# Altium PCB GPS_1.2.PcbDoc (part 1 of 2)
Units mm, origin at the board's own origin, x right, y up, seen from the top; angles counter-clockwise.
Board outline 48.01 x 70.36 mm, 4 copper layers (Top Layer, GND, VDD, Bottom Layer); 58 components, 49 nets, 268 pads, 156 vias.
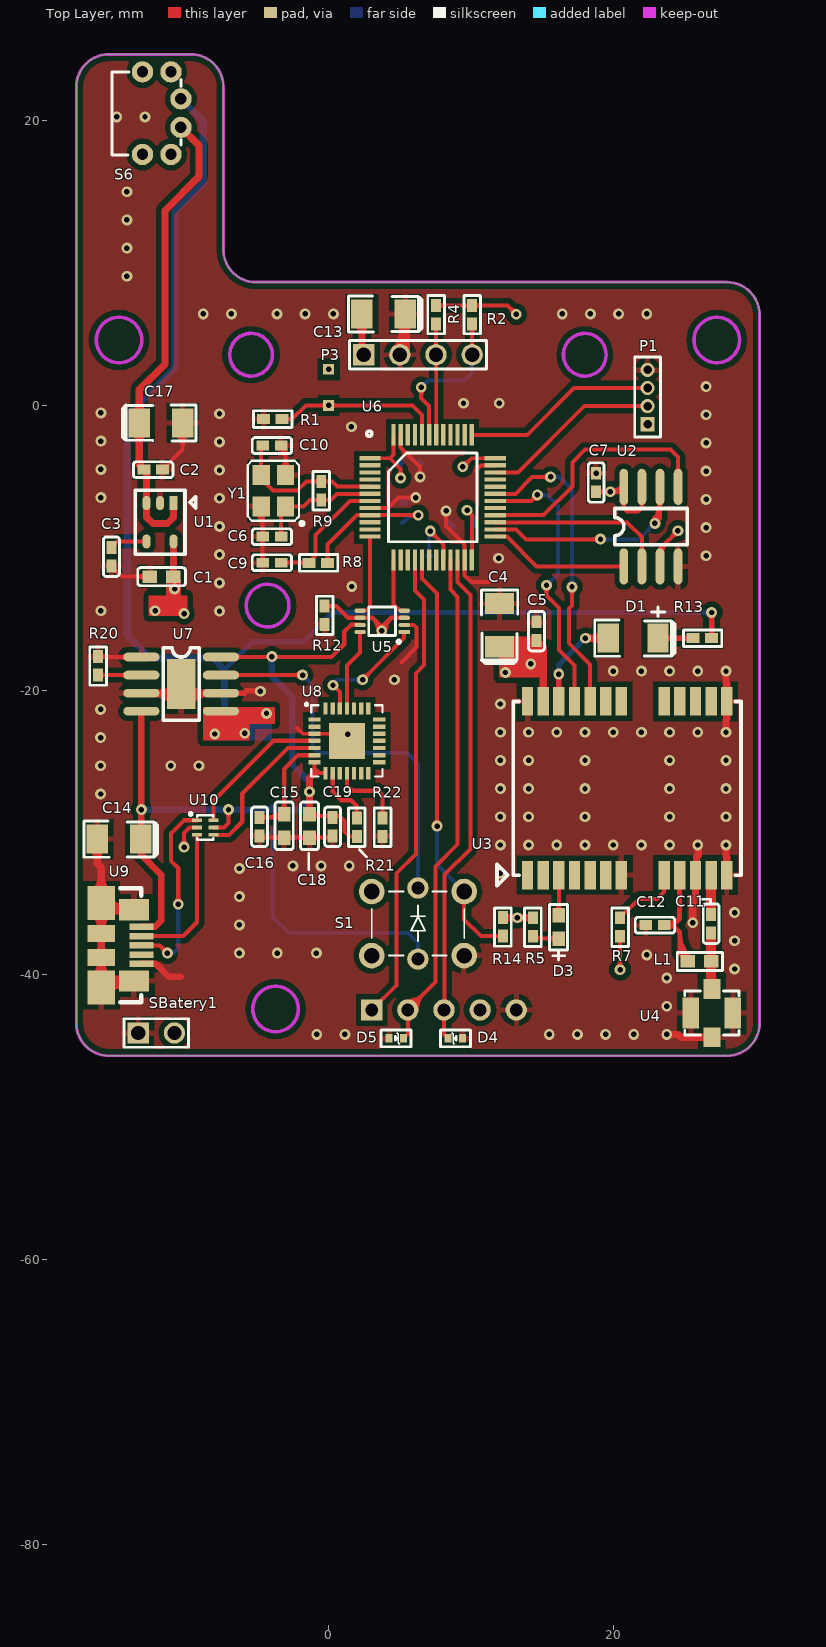
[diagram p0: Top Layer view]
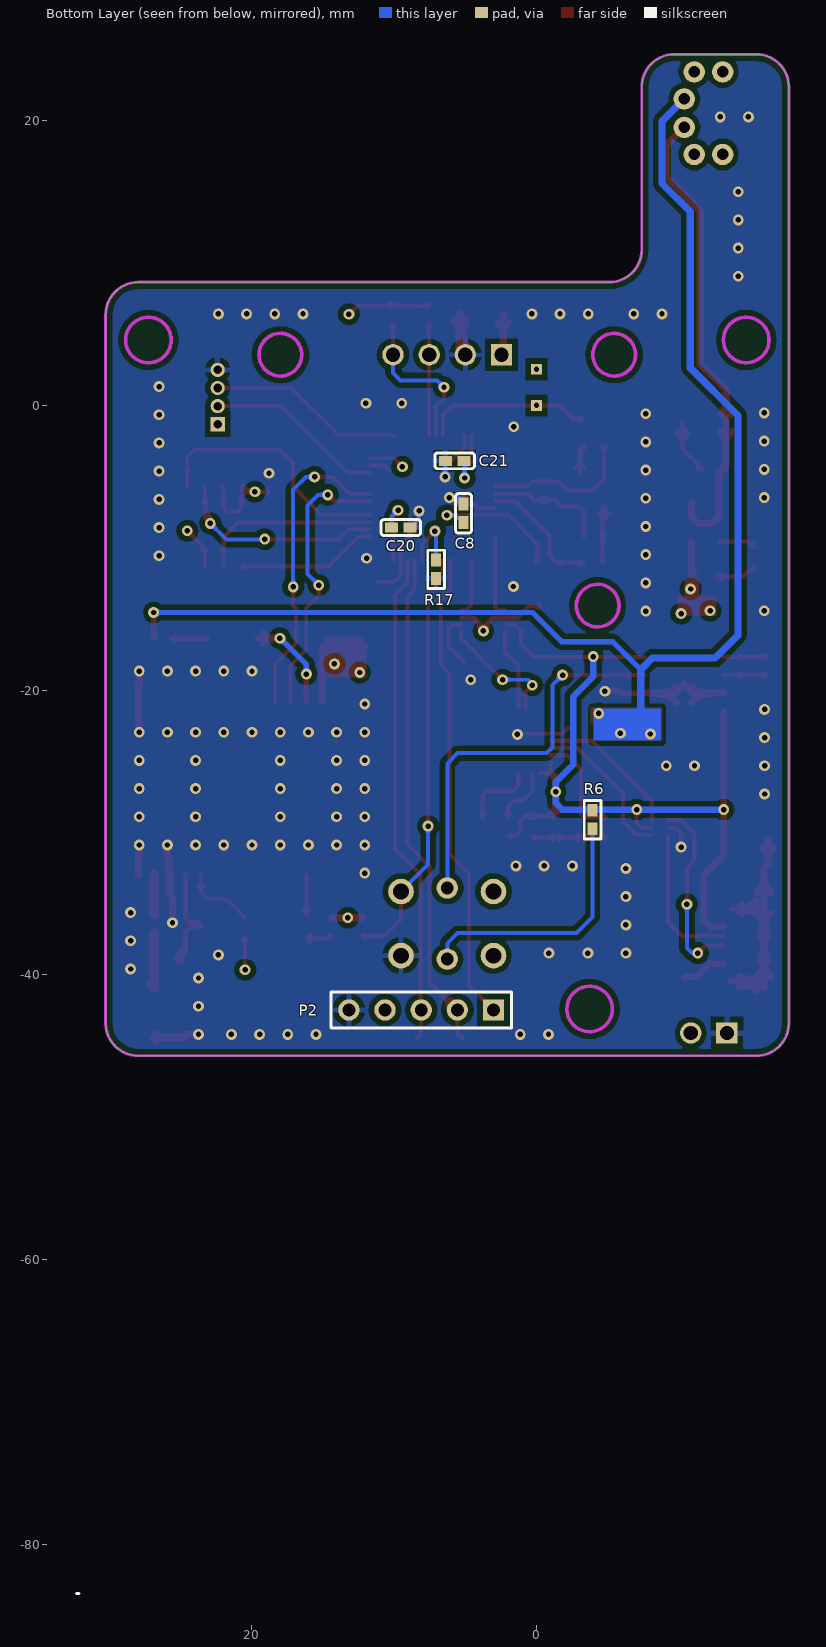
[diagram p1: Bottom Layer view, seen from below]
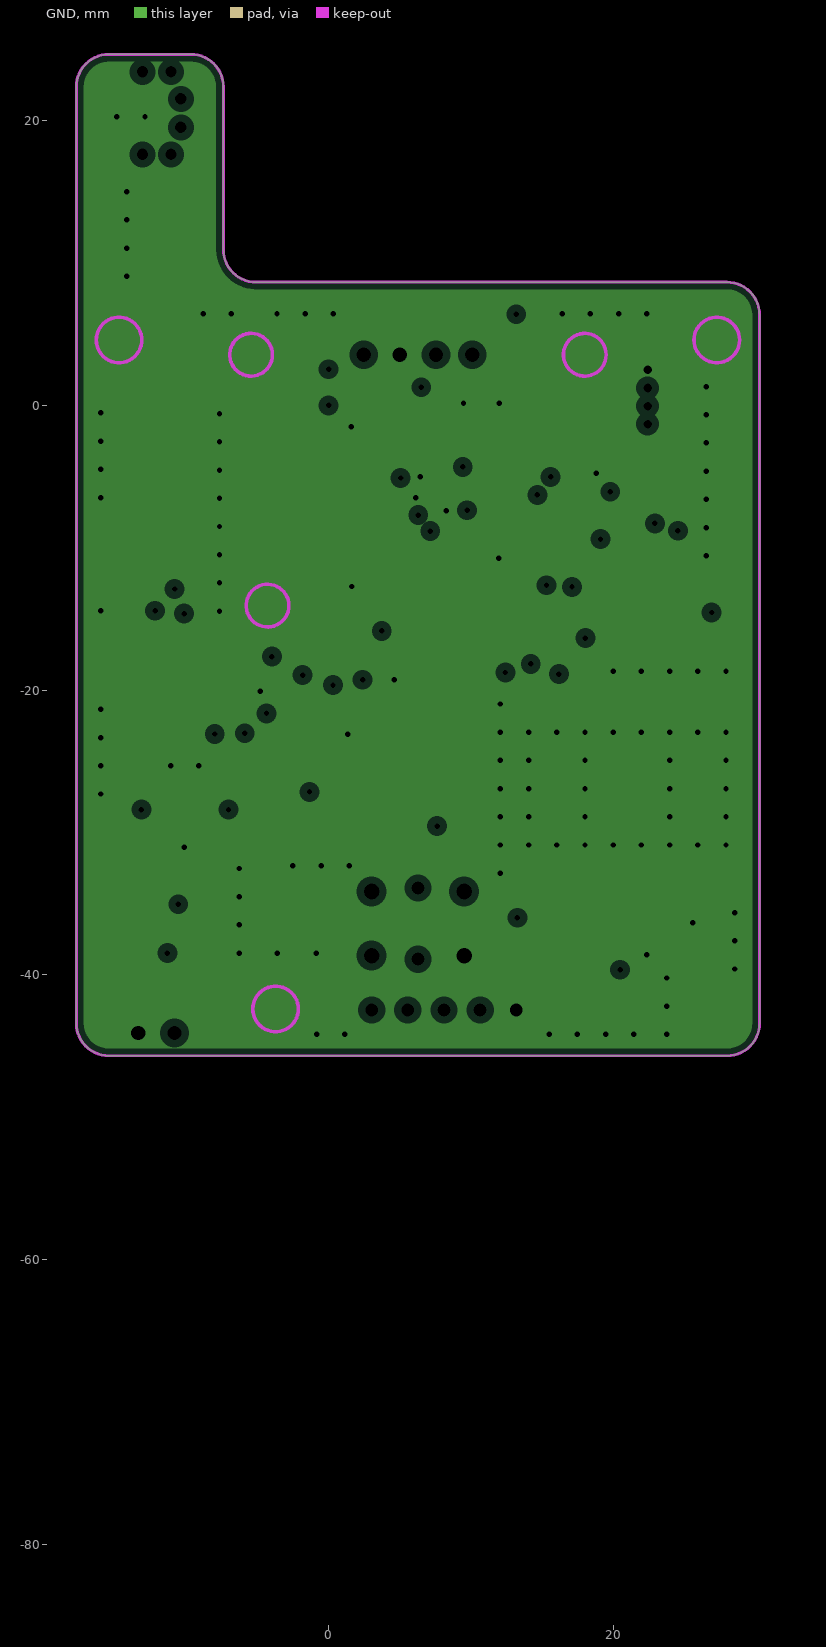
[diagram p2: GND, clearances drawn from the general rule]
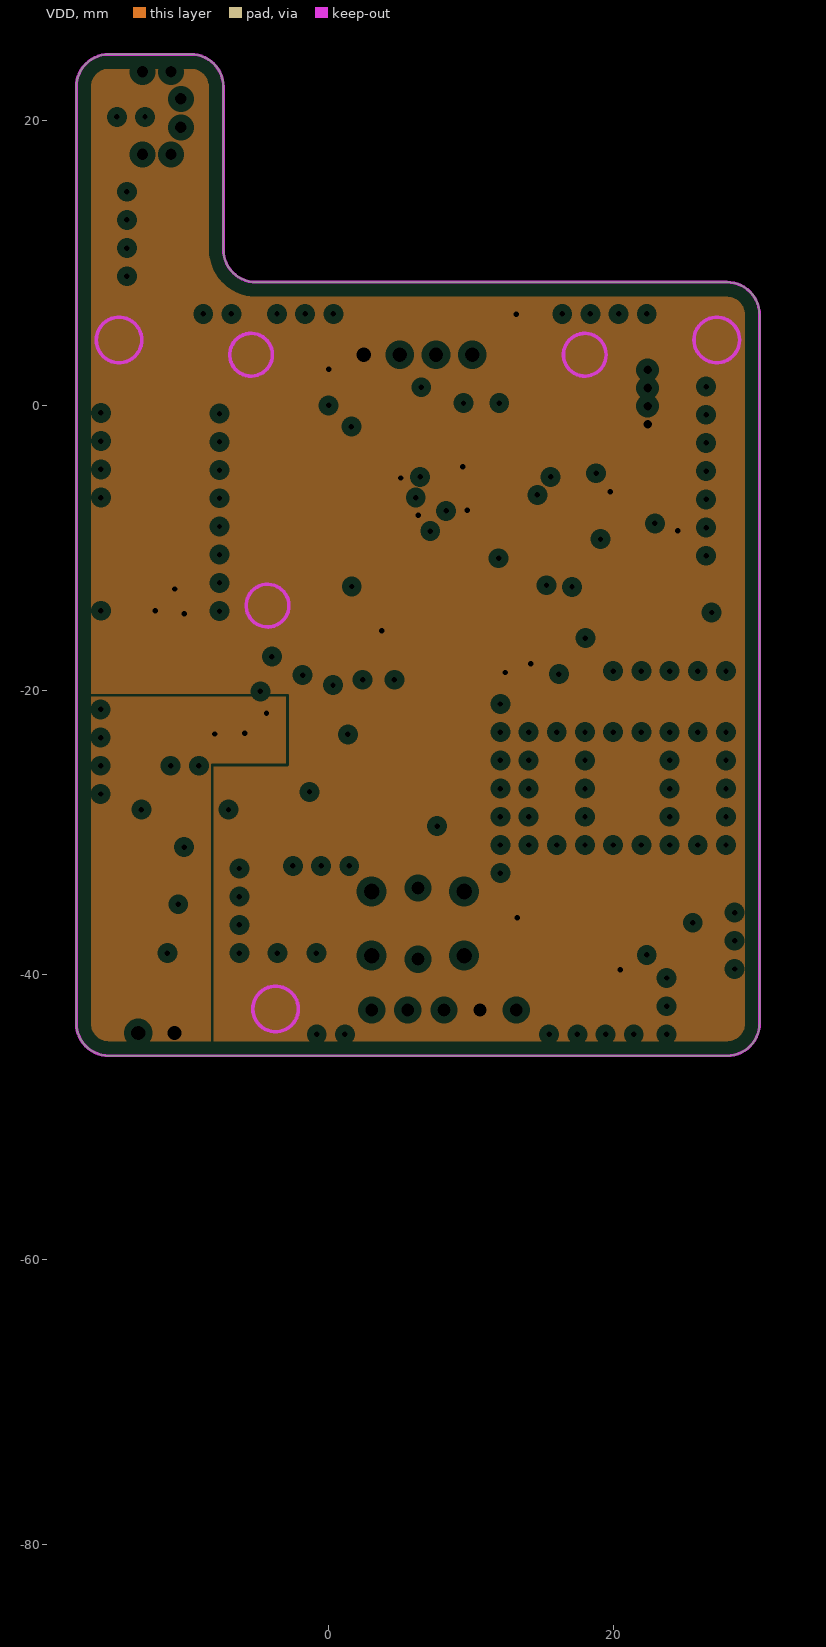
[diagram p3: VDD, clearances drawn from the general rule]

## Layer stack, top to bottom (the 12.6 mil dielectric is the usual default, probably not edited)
Top Layer: signal copper 0.0356
Dielectric: core 0.32, FR-4, Dk 4.8
GND: plane copper 0.0356, net GND
Dielectric: prepreg 0.32, FR-4, Dk 4.8
VDD: plane copper 0.0356, net VDD
Dielectric: core 0.32, FR-4, Dk 4.8
Bottom Layer: signal copper 0.0356

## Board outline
-17.729,-43.409 -17.729,22.377 cw(c-15.443,22.377) -15.443,24.663 -9.677,24.663 cw(c-9.677,22.377) -7.391,22.377 -7.391,10.939 ccw(c-5.105,10.939) -5.105,8.653 27.985,8.653 cw(c27.985,6.367) 30.271,6.367 30.271,-43.409 30.277,-43.409 cw(c27.991,-43.409) 27.991,-45.695 -15.443,-45.695 cw(c-15.443,-43.409)

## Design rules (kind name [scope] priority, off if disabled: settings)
Clearance Clearance_1 [OnLayer('Keep-Out Layer')] p1 off: gap=0.508
Clearance Clearance_RF [InNetClass('RF')] p2 off: gap=0.508
Clearance [All] p3: gap=0.381
DiffPairsRouting [All] p1: maxlimit=0.254 minlimit=0.254 mostfreqgap=0.254 maxuncoupledlength=12.7
HoleSize [All] p1 off: absolutevalues=TRUE maxlimit=2.54 minlimit=0.025 maxpercent=80.000 minpercent=20.000
HoleToHoleClearance [All] p1 off: gap=0.254 allowstackedmicrovias=TRUE
LayerPairs [All] p1 off: enforce=TRUE
MinimumSolderMaskSliver [All] p1 off: minsoldermaskwidth=0.254
NetAntennae [All] p1 off: netantennaetolerance=0
PlaneClearance [All] p1: clearance=0.508
PlaneConnect [All] p1: planeconnectstyle=Relief reliefexpansion=0.508 reliefentries=4 reliefconductorwidth=0.381 reliefairgap=0.254
PolygonConnect PolygonConnect_1 [(InPadClass('All Pads'))] p1: connectstyle=Relief reliefconductorwidth=0.381 reliefentries=4 polygonreliefangle="90 Angle"
PolygonConnect [All] p2: connectstyle=Direct reliefconductorwidth=0.381 reliefentries=4 polygonreliefangle="90 Angle"
RoutingVias [All] p1: holewidth=0.711 width=1.27 viastyle="Through Hole" minholewidth=0 minwidth=0 maxholewidth=0.711 maxwidth=1.27
SilkToSilkClearance [All] p1 off: silktosilkclearance=0.254
SilkscreenOverComponentPads [All] p1 off: minsilkscreentomaskgap=0.254
SolderMaskExpansion [All] p1: expansion=0.102
Width [All] p1: maxlimit=1.27 minlimit=0.279 preferedwidth=0.279
18 further rules are at their usual default settings.

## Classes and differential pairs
net class RF: NetC11_1 RF_IN
differential pair D: +D_P -D_N

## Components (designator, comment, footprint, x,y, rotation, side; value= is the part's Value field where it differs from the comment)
C1 "10uF/10V" C0603 -11.735,-12.04 r0 top
C2 "0.1uF/10V" C0402 -12.979,-4.521 r180 top
C3 "0.01uF/10V" C0402 -15.265,-9.982 r90 top
C4 "10uF/10V" 3528 12.014,-16.967 r90 top
C5 "0.1uF/10V" C0402 14.605,-16.51 r270 top
C6 "18pF/10V" C0402 -4.635,-9.228 r180 top
C7 "0.01uF/10V" C0402 18.796,-6.071 r270 top
C8 "0.01uF/10V" C0402 5.131,-8.238 r270 bottom
C9 "0.01uF/10V" C0402 -4.635,-11.057 r180 top
C10 "18pF/10V" C0402 -3.335,-2.827 r0 top
C11 "470pF" C0402 26.873,-37.067 r270 top
C12 "33nF" C0402 22.276,-36.525 r180 top
C13 "10uF/10V" C1206 3.861,6.426 r180 top
C14 "10uF/10V" 3528 -13.208,-30.48 r180 top
C15 "4.7uF/10V" C0603 -3.124,-29.54 r90 top
C16 "0.1uF/10V" C0402 -4.851,-28.956 r90 top
C17 "10uF/10V" 3528 -13.31,-1.245 r0 top
C18 "10uF/10V" C0603 -1.346,-29.54 r270 top
C19 "0.1uF/10V" C0402 0.279,-28.956 r90 top
C20 "0.01uF/10V" C0402 10.185,-8.585 r0 bottom
C21 "0.01uF/10V" C0402 5.105,-3.894 r180 bottom
D1 "IN4148" L1206 23.139,-16.358 r180 top
D3 "LED0" LED0603 16.154,-37.473 r90 top
D4 "PESD0402-140" 0402-TVS 8.077,-44.425 r180 top
D5 "PESD0402-140" 0402-TVS 5.563,-44.526 r0 top
L1 "6.8nH" R0603 26.06,-39.065 r180 top
P1 "MHDR1X4" SIP4_1.27 22.403,-1.321 r0 top
P2 "Header 5" HDR1X5 3.023,-42.477 r0 bottom
P3 "MHDR1X4" OLED 6.271,3.556 r0 top locked
R1 "10K/5%" R0402 -3.272,-0.965 r0 top
R2 "5.1K/5%" R0402 10.084,5.715 r270 top
R4 "5.1K/5%" R0402 7.544,5.715 r270 top
R5 "510R/5%" R0402 14.351,-36 r90 top
R6 "1K/5%" R0402 -3.937,-28.448 r90 bottom
R7 "10K/5%" R0402 20.472,-36 r90 top
R8 "10K/5%" R0402 -1.372,-11.074 r180 top
R9 "1M/5%" R0402 -0.521,-5.342 r90 top
R12 "10K/5%" R0402 -0.279,-14.097 r90 top
R13 "105K/5%" R0402 25.603,-16.358 r180 top
R14 "10K/5%" R0402 12.243,-35.992 r90 top
R17 "10K/5%" R0402 7.058,-10.866 r90 bottom
R20 "2K/5%" R0402 -16.205,-17.653 r90 top
R21 "1K/5%" R0402 1.981,-28.981 r90 top
R22 "10K/5%" R0402 3.785,-28.981 r90 top
S1 "KEY_TONE_LED" KEY_TONE_LED 6.271,-36.409 r180 top locked (schematic designator U1)
S6 "SW-PB" KEY1 -10.379,19.53 r90 top locked
SBatery1 "SBatery" SIP2 -13.376,-44.094 r0 top
U1 "TPS73633DBVR" SOP5-TPS73633DBVR -10.897,-6.858 r270 top
U2 "FM25V01" SO-8 20.739,-11.311 r90 top
U3 "NEO-M8N" NEO-M8N 13.97,-33.003 r0 top locked
U4 "antenna" "Active antenna" 26.924,-42.697 r90 top locked
U5 "TXS0102" R-PDSO-G8 5.309,-15.926 r180 top
U6 "STM32F10xC8T6" LQFP-48 2.908,-3.716 r0 top
U7 "TP4056" SO-8-1 -10.363,-19.583 r0 top
U8 "CP2102" QFN-28 -0.991,-22.073 r0 top
U9 "USB" MOLEX-47346-0001 -13.157,-36.627 r270 top
U10 "NUF2042XV6T1" UDFN -9.246,-29.159 r270 top
Y1 "16MHz" OSCILLATOR-3.2X2.5 -3.886,-5.994 r180 top

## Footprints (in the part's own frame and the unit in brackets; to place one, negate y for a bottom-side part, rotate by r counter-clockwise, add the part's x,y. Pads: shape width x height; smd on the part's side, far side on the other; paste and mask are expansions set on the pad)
0402-TVS [mil]
  rect 20x24 smd: 1(-52,2) 2(-12.31,2)
  silkscreen extent -74,-21 9,25
3528 [mil]
  rect 59.05x80 smd: 1(0,0) 2(120,0)
  silkscreen extent -46,-50 157,50
"Active antenna" [mm]
  rect 1.4x1.2 smd: 0(-1.7,0) 1(1.7,0)
  rect 2.2x1.15 smd: 0(0,1.475) 0(0,-1.475)
  silkscreen extent -1.55,-1.91 1.55,1.91
C0402 [mm]
  rect 0.9x0.7 smd: 1(0,0) 2(-1.3,0)
  silkscreen extent -2.04,-0.56 0.74,0.56
C0603 [mil]
  rect 40x35 smd: 1(-32.5,0) 2(32.5,0)
  silkscreen extent -66,-25 66,25
C1206 [mil]
  rect 59.05x80 smd: 1(-60,0) 2(60,0)
  silkscreen extent -106,-50 97,50
HDR1X5 [mm] "Connector; Header; 5 Position"
  rect 1.5x1.5 hole 0.9: 1(0,0)
  round 1.5 hole 0.9: 2(2.54,0) 3(5.08,0) 4(7.62,0) 5(10.16,0)
  silkscreen extent -1.27,-1.27 11.43,1.27
KEY1 [mm]
  round 1.5 hole 0.8: 0(-1.9,0.7) 0(-1.9,2.7) 0(3.9,0.7) 0(3.9,2.7) 1(0,0) 2(2,0)
  silkscreen extent -1.93,0 3.89,4.85
KEY_TONE_LED [mm]
  round 0.2 on Top Overlay: 0(0,0)
  round 1.8 hole 1.1: 1(-3.25,2.25) 2(3.25,2.25) 3(-3.25,-2.25) 4(3.25,-2.25)
  round 1.5 hole 0.9: 5(0,-2.5) 6(0,2.5)
  silkscreen extent -3.25,-2.25 3.25,2.25
L1206 [mm]
  rect 1.5x2.032 smd: 1(0,0) 2(3.5,0)
  silkscreen extent -1.16,-1.27 4.45,1.27
LED0603 [mil]
  rect 40x35 smd: 1(0,0) 2(65,0)
  silkscreen extent -59,-25 94,25
LQFP-48 [mm]
  rect 1.5x0.3 smd: 1(0,0) 2(0,-0.5) 3(0,-1) 4(0,-1.5) 5(0,-2) 6(0,-2.5) 7(0,-3) 8(0,-3.5) 9(0,-4) 10(0,-4.5) 11(0,-5) 12(0,-5.5) 25(8.8,-5.5) 26(8.8,-5) 27(8.8,-4.5) 28(8.8,-4) 29(8.8,-3.5) 30(8.8,-3) 31(8.8,-2.5) 32(8.8,-2) 33(8.8,-1.5) 34(8.8,-1) 35(8.8,-0.5) 36(8.8,0)
  rect 0.3x1.5 smd: 13(1.65,-7.15) 14(2.15,-7.15) 15(2.65,-7.15) 16(3.15,-7.15) 17(3.65,-7.15) 18(4.15,-7.15) 19(4.65,-7.15) 20(5.15,-7.15) 21(5.65,-7.15) 22(6.15,-7.15) 23(6.65,-7.15) 24(7.15,-7.15) 37(7.15,1.65) 38(6.65,1.65) 39(6.15,1.65) 40(5.65,1.65) 41(5.15,1.65) 42(4.65,1.65) 43(4.15,1.65) 44(3.65,1.65) 45(3.15,1.65) 46(2.65,1.65) 47(2.15,1.65) 48(1.65,1.65)
  silkscreen extent -0.24,-5.86 7.51,1.91
MOLEX-47346-0001 [mil]
  rect 18x67 smd: 1(0,0) 2(26,0) 3(52,0) 4(77.59,0) 5(103.18,0)
  rect 94x75 smd: 6(-65,-111) 9(168.14,-111)
  rect 59x83 smd: 7(-47,-20) 8(150.43,-20)
  rect 47x75 smd: 10(84.97,-111) 11(19,-111)
  silkscreen extent -106,-59 209,0
NEO-M8N [mm]
  rect 0.8x2 smd: 1(0,0) 2(1.1,0) 3(2.2,0) 4(3.3,0) 5(4.4,0) 6(5.5,0) 7(6.6,0) 8(9.6,0) 9(10.7,0) 10(11.8,0) 11(12.9,0) 12(14,0) 13(14,12.2) 14(12.9,12.2) 15(11.8,12.2) 16(10.7,12.2) 17(9.6,12.2) 18(6.6,12.2) 19(5.5,12.2) 20(4.4,12.2) 21(3.3,12.2) 22(2.2,12.2) 23(1.1,12.2) 24(0,12.2)
  silkscreen extent -2.14,-0.76 15,12.2
OLED [mm]
  rect 1.5x1.5 hole 1: 1(-3.81,0)
  round 1.5 hole 1: 2(-1.27,0) 3(1.27,0) 4(3.81,0)
  Keep-Out Layer circle w0.254: c11.725,0 r1.5
  Keep-Out Layer circle w0.254: c-11.725,0 r1.5
  silkscreen extent -4.81,-1 4.81,1
OSCILLATOR-3.2X2.5 [mil]
  rect 48x56 smd: 1(-33.73,43.65) 2(-33.73,-43.65) 3(33.73,-43.65) 4(33.73,43.65)
  silkscreen extent -83,-83 71,95
QFN-28 [mil]
  rect 34x12 smd mask+5: 1(0,0) 2(0,-19.68) 3(0,-39.37) 4(0,-59.06) 5(0,-78.74) 6(0,-98.43) 7(0,-118.11) 15(179,-118.11) 16(179,-98.43) 17(179,-78.74) 18(179,-59.06) 19(179,-39.37) 20(179,-19.69) 21(179,0)
  rect 12x34 smd mask+5: 8(30.44,-148.56) 9(50.13,-148.56) 10(69.81,-148.56) 11(89.5,-148.56) 12(109.19,-148.56) 13(128.87,-148.56) 14(148.56,-148.56) 22(148.56,30.44) 23(128.87,30.44) 24(109.19,30.44) 25(89.5,30.44) 26(69.82,30.44) 27(50.13,30.44) 28(30.44,30.44)
  rect 100x100 smd mask+5: 29(89.5,-59.06)
  silkscreen extent -25,-158 188,44
R0402 [mm]
  rect 0.9x0.7 smd: 1(0,0) 2(-1.3,0)
  silkscreen extent -2.01,-0.58 0.69,0.58
R0603 [mil]
  rect 40x35 smd: 1(-32.5,0) 2(32.5,0)
  silkscreen extent -63,-25 62,25
R-PDSO-G8 [mm]
  rect 0.8x0.3 smd: 1(0,0)
  oval 0.8x0.3 smd: 2(0,-0.5) 3(0,-1) 4(0,-1.5) 5(3.1,-1.5) 6(3.1,-1) 7(3.1,-0.5) 8(3.1,0)
  silkscreen extent 0.29,-1.75 2.49,0.78
SIP2 [mm]
  rect 1.5x1.5 hole 1: 1(0,0)
  round 1.5 hole 1: 2(2.54,0)
  silkscreen extent -1,-1 3.54,1
SIP4_1.27 [mm]
  rect 1x1 hole 0.6: 1(0,0)
  round 1 hole 0.6: 2(0,1.27) 3(0,2.54) 4(0,3.81)
  silkscreen extent -0.9,-0.9 0.9,4.71
SO-8 [mil]
  oval 100x24 smd: 1(0,0) 2(0,-50) 3(0,-100) 4(0,-150) 5(220,-150) 6(220,-100) 7(220,-50) 8(220,0)
  silkscreen extent 60,-175 160,25
SO-8-1 [mil]
  rect 78.74x137.8 smd: 0(0,0)
  oval 100x24 smd: 1(-110,75) 2(-110,25) 3(-110,-25) 4(-110,-75) 5(110,-75) 6(110,-25) 7(110,25) 8(110,75)
  silkscreen extent -50,-100 50,100
SOP5-TPS73633DBVR [mm]
  rect 1x0.55 smd: 1(0,0)
  oval 1x0.55 smd: 2(0,-0.95) 3(0,-1.9) 4(2.7,-1.9) 5(2.7,0)
  silkscreen extent -0.9,-2.7 3.6,1.55
UDFN [mm]
  rect 0.25x0.7 smd: 1(0,0) 2(0.5,0) 3(1,0) 4(1,1.15) 5(0.5,1.15) 6(0,1.15)
  silkscreen extent -0.55,-0.55 1.35,1.15

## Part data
C1 C2 C3 C4 C5 C6 C7 C8 C9 C10 C11 C12 C15 C16 C18 C19 C20 C21: library part Cap, "Capacitor"
C13 C14 C17: library part "Cap Pol2", "Polarized Capacitor (Axial)"
D1: library part ZENER2, "Zener Diode"
D3: "Typical INFRARED GaAs LED"
D4 D5: library part "D Zener", "Zener Diode"
L1: library part Inductor, "Inductor"
P1 P3: "Header, 4-Pin"
P2: "Header, 5-Pin"
R1 R2 R4 R5 R6 R7 R8 R9 R12 R13 R14 R17 R20: library part Res2, "Resistor"
R21 R22: library part Resistor, "Resistor SMD - IEC symbol version"
S6: "Switch"
U2: library part FM25CL64B
U6: library part STM32F100C8T6
U8: "Imported"
U9: library part MICRO_USB
Y1: library part XTAL3

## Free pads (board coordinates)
  rect 0.762x0.762 hole 0.381: 0(0,2.54) 1(0,0)

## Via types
v1: diameter 0.762, hole 0.381, Top Layer to Bottom Layer, 156 vias

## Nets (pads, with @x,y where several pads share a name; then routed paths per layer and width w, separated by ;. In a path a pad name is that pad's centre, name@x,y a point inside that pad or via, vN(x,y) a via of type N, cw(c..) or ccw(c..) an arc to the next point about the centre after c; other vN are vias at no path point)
BAT: R13.2 S6.2 SBatery1.2 U7.5 | length 93.2
  Top Layer w0.381: R13.2@26.903,-16.358 v1(26.903,-14.554) ; 26.903,-15.973 cw(c26.518,-15.973) 26.79,-16.245 ccw(c26.518,-15.973) 26.903,-15.973 ; 26.903,-15.973 ccw(c27.288,-15.973) 27.016,-16.245 cw(c27.288,-15.973) 26.903,-15.973 ; 26.903,-15.014 cw(c27.363,-15.014) 27.038,-14.689 ccw(c27.363,-15.014) 26.903,-15.014 ; 26.903,-15.014 ccw(c26.443,-15.014) 26.768,-14.689 cw(c26.443,-15.014) 26.903,-15.014
  Bottom Layer w0.381: -7.315,-18.567 -5.359,-16.612 -1.778,-16.612 0.279,-14.554 v1(26.903,-14.554) ; 26.443,-14.554 cw(c26.443,-15.014) 26.768,-14.689 ccw(c26.443,-15.014) 26.443,-14.554 ; 26.443,-14.554 ccw(c26.443,-14.094) 26.768,-14.419 cw(c26.443,-14.094) 26.443,-14.554
  Bottom Layer w0.508: S6.2@-10.379,21.53 -8.814,19.964 -8.814,15.596 -10.795,13.614 -10.795,2.642 -14.148,-0.711 -14.148,-16.154 -12.548,-17.755 -8.128,-17.755 -7.315,-18.567 -7.315,-21.641
  other v1: -8.001,-23.089 -5.893,-23.038 -4.369,-21.641
CHRG: S1.5 U7.7 | length 32.6
  Top Layer w0.279: U7.7@-7.569,-18.948 v1(-1.829,-18.948) ; -6.205,-18.948 cw(c-6.205,-18.55) -6.487,-18.832 ccw(c-6.205,-18.55) -6.205,-18.948 ; -6.205,-18.948 ccw(c-6.205,-19.347) -6.487,-19.065 cw(c-6.205,-19.347) -6.205,-18.948 ; -2.411,-18.948 cw(c-2.411,-19.531) -1.999,-19.119 ccw(c-2.411,-19.531) -2.411,-18.948 ; -2.411,-18.948 ccw(c-2.411,-18.366) -1.999,-18.778 cw(c-2.411,-18.366) -2.411,-18.948
  Bottom Layer w0.279: v1(-1.829,-18.948) -1.118,-19.66 -1.118,-24.028 -0.711,-24.435 5.537,-24.435 6.271,-25.168 S1.5@6.271,-33.909 ; -1.417,-19.36 cw(c-1.005,-18.948) -1.587,-18.948 ccw(c-1.005,-18.948) -1.417,-19.36 ; -1.417,-19.36 ccw(c-1.829,-19.772) -1.829,-19.19 cw(c-1.829,-19.772) -1.417,-19.36
D_N: U8.5 U10.4 | length 10.8
  Top Layer w0.305: U10.4@-8.096,-30.191 -7,-30.191 -6.071,-29.261 -6.071,-27.28 -2.864,-24.073 U8.5@-0.991,-24.073
D_P: U8.4 U10.6 | length 10.2
  Top Layer w0.305: U10.6@-8.096,-29.128 -8.096,-27.781 -3.888,-23.573 U8.4@-0.991,-23.573
FRAM_CLK: U2.6 U6.26 | length 28.1
  Top Layer w0.279: U6.26@11.708,-8.716 13.161,-8.716 13.876,-9.431 19.067,-9.431 v1(19.101,-9.398) ; v1@22.883,-8.051 ccw(c22.794,-7.53) 23.252,-7.794 ; v1@22.89,-8.306 cw(c23.292,-8.094) 22.898,-7.867 ; v1(22.924,-8.288) 23.279,-7.933 ; U2.6@23.136,-6.771 cw(c22.669,-7.04) 23.19,-7.18 ; v1@23.137,-8.176 cw(c23.819,-7.815) 23.151,-7.429 ; v1@23.157,-8.226 cw(c23.598,-8.108) 23.202,-7.879 ; U2.6@23.279,-5.723 23.279,-7.933 ; 23.279,-7.933 cw(c22.994,-7.648) 22.95,-8.049 ccw(c22.994,-7.648) 23.279,-7.933 ; 23.279,-7.933 ccw(c23.564,-8.218) 23.163,-8.262 cw(c23.564,-8.218) 23.279,-7.933 ; 23.279,-7.087 cw(c23.678,-7.087) 23.396,-6.805 ccw(c23.678,-7.087) 23.279,-7.087 ; 23.279,-7.087 ccw(c22.881,-7.087) 23.162,-6.805 cw(c22.881,-7.087) 23.279,-7.087 ; 18.438,-9.431 ccw(c18.438,-8.735) 18.93,-9.227 cw(c18.438,-8.735) 18.438,-9.431 ; 18.599,-9.431 cw(c18.599,-9.9) 18.93,-9.569 ccw(c18.599,-9.9) 18.599,-9.431 ; v1@22.753,-8.118 ccw(c21.483,-6.847) 23.279,-6.847 cw(c21.483,-6.847) v1@22.753,-8.118 ; v1@22.951,-8.315 ccw(c22.157,-7.522) 23.279,-7.522 cw(c22.157,-7.522) v1@22.951,-8.315
  Bottom Layer w0.279: v1@19.101,-9.431 21.781,-9.431 v1(22.924,-8.288) ; 22.512,-8.7 cw(c22.924,-9.112) 22.924,-8.53 ccw(c22.924,-9.112) 22.512,-8.7 ; 22.512,-8.7 ccw(c22.1,-8.288) 22.682,-8.288 cw(c22.1,-8.288) 22.512,-8.7
FRAM_CS: U2.1 U6.25 | length 11.2
  Top Layer w0.279: U6.25@11.708,-9.216 12.518,-9.216 14.613,-11.311 U2.1@20.739,-11.311 ; 20.341,-11.311 cw(c20.341,-11.71) 20.622,-11.428 ccw(c20.341,-11.71) 20.341,-11.311 ; 20.341,-11.311 ccw(c20.341,-10.912) 20.622,-11.194 cw(c20.341,-10.912) 20.341,-11.311
FRAM_MISO: U2.2 U6.27 | length 14
  Top Layer w0.279: U6.27@11.708,-8.216 20.967,-8.216 22.009,-9.258 U2.2@22.009,-11.311 ; 22.009,-9.947 cw(c21.611,-9.947) 21.892,-10.229 ccw(c21.611,-9.947) 22.009,-9.947 ; 22.009,-9.947 ccw(c22.408,-9.947) 22.126,-10.229 cw(c22.408,-9.947) 22.009,-9.947
FRAM_MOSI: U2.5 U6.28 | length 19.3
  Top Layer w0.279: U6.28@11.708,-7.716 15.093,-7.716 17.12,-5.69 17.12,-4.009 18.021,-3.107 24.016,-3.107 24.549,-3.64 U2.5@24.549,-5.723 ; 24.549,-4.359 cw(c24.151,-4.359) 24.432,-4.641 ccw(c24.151,-4.359) 24.549,-4.359 ; 24.549,-4.359 ccw(c24.948,-4.359) 24.666,-4.641 cw(c24.948,-4.359) 24.549,-4.359
GND: C1.1 C2.2 C3.2 C4.2 C5.2 C6.1 C7.2 C8.2 C9.1 C10.1 C12.1 C13.1 C14.2 C15.1 C16.2 C17.2 C18.2 C19.2 C20.2 C21.2 D4.1 D5.1 P1.4 P2.5 P3.2 R1.2 R12.2 R17.2 R20.1 R22.2 S1.1 SBatery1.1 U1.2 U2.4 U3.7 U3.10 U3.12 U3.13 U3.24 U4.0 U5.2 U6.8 U6.23 U6.35 U6.47 U7.0 U7.1 U7.3 U7.6 U8.3 U8.29 U9.5 U9.6 U9.7 U9.8 U9.9 U9.10 U9.11 U10.2 Y1.2 Y1.4 | length 256.5
  Top Layer w0.279: U9.6@-15.977,-34.976 -15.519,-35.433 U9.7@-13.665,-35.433 ; C3.2@-15.265,-11.282 -14.508,-12.04 C1.1@-12.56,-12.04 ; C2.2@-11.679,-4.521 -10.262,-3.103 C17.2@-10.262,-1.245 ; C16.2@-4.851,-30.256 -4.742,-30.366 C15.1@-3.124,-30.366 C18.2@-1.346,-30.366 0.17,-30.366 C19.2@0.279,-30.256 ; v1@-4.826,-20.066 v1(-4.801,-20.091) ; Y1.4@-4.743,-7.103 -4.635,-7.211 C6.1@-4.635,-9.228 C9.1@-4.635,-11.057 ; C10.1@-3.335,-2.827 -3.029,-3.133 Y1.2@-3.029,-4.886 ; -3.129,-3.417 cw(c-2.799,-3.227) C10.1@-3.08,-2.969 ; -2.21,-22.657 -1.794,-23.073 U8.3@-0.991,-23.073 U8.29@0.783,-23.073 ; U6.8@2.908,-7.216 4.163,-7.216 4.902,-6.477 v1(6.121,-6.477) ; U6.47@5.058,-2.066 5.058,-2.976 6.426,-4.343 v1(6.426,-5.029) ; 5.105,-18.059 6.172,-16.993 6.172,-15.621 5.977,-15.426 U5.2@5.309,-15.426 ; v1(8.255,-7.417) 8.255,-8.484 9.558,-9.787 U6.23@9.558,-10.866 9.558,-11.946 10.033,-12.421 11.227,-12.421 ; 10.363,-4.572 10.719,-4.216 U6.35@11.708,-4.216 ; U9.6@-15.442,-35.433 cw(c-15.442,-36.905) -14.401,-35.864 ccw(c-15.442,-36.905) U9.6@-15.442,-35.433 ; U9.6@-15.442,-35.433 ccw(c-15.442,-33.961) -14.401,-35.002 cw(c-15.442,-33.961) U9.6@-15.442,-35.433 ; -15.019,-35.238 cw(c-15.208,-35.943) -14.534,-35.665 ccw(c-15.208,-35.943) -15.019,-35.238 ; -15.019,-35.238 ccw(c-14.876,-34.704) -14.445,-35.051 cw(c-14.876,-34.704) -15.019,-35.238 ; -14.946,-35.09 cw(c-15.078,-35.58) -14.574,-35.513 ccw(c-15.078,-35.58) -14.946,-35.09 ; -14.946,-35.09 ccw(c-14.776,-34.454) -14.357,-34.962 cw(c-14.776,-34.454) -14.946,-35.09 ; -14.903,-35.532 cw(c-14.816,-35.857) -14.515,-35.706 ccw(c-14.816,-35.857) -14.903,-35.532 ; -14.903,-35.532 ccw(c-15.045,-35.001) -14.536,-35.206 cw(c-15.045,-35.001) -14.903,-35.532 ; -14.767,-35.433 cw(c-14.767,-36.23) -14.203,-35.666 ccw(c-14.767,-36.23) -14.767,-35.433 ; -14.767,-35.433 ccw(c-14.767,-34.636) -14.203,-35.2 cw(c-14.767,-34.636) -14.767,-35.433 ; U9.7@-14.589,-35.662 cw(c-14.374,-34.861) -15.183,-35.041 ccw(c-14.374,-34.861) U9.7@-14.589,-35.662 ; U9.7@-14.589,-35.662 ccw(c-14.844,-36.613) -15.464,-35.848 cw(c-14.844,-36.613) U9.7@-14.589,-35.662 ; U9.7@-13.665,-35.433 cw(c-13.665,-33.135) -15.373,-34.673 ccw(c-13.665,-33.135) U9.7@-13.665,-35.433 ; -13.36,-12.04 cw(c-13.36,-12.775) -12.839,-12.255 ccw(c-13.36,-12.775) -13.36,-12.04 ; -13.36,-12.04 ccw(c-13.36,-11.304) -12.839,-11.824 cw(c-13.36,-11.304) -13.36,-12.04 ; -10.262,-2.984 cw(c-8.788,-2.984) -9.83,-1.942 ccw(c-8.788,-2.984) -10.262,-2.984 ; -10.262,-2.984 ccw(c-11.735,-2.984) -10.693,-1.942 cw(c-11.735,-2.984) -10.262,-2.984 ; -10.262,-2.309 cw(c-9.463,-2.309) -10.028,-1.745 ccw(c-9.463,-2.309) -10.262,-2.309 ; -10.262,-2.309 ccw(c-11.06,-2.309) -10.496,-1.745 cw(c-11.06,-2.309) -10.262,-2.309 ; -4.635,-10.549 cw(c-5.143,-10.549) -4.784,-10.908 ccw(c-5.143,-10.549) -4.635,-10.549 ; -4.635,-10.549 ccw(c-4.128,-10.549) -4.487,-10.908 cw(c-4.128,-10.549) -4.635,-10.549 ; -4.635,-9.736 cw(c-4.128,-9.736) -4.487,-9.377 ccw(c-4.128,-9.736) -4.635,-9.736 ; -4.635,-9.736 ccw(c-5.143,-9.736) -4.784,-9.377 cw(c-5.143,-9.736) -4.635,-9.736 ; -4.635,-8.72 cw(c-5.143,-8.72) -4.784,-9.079 ccw(c-5.143,-8.72) -4.635,-8.72 ; -4.635,-8.72 ccw(c-4.128,-8.72) -4.487,-9.079 cw(c-4.128,-8.72) -4.635,-8.72 ; -3.86,-30.366 cw(c-3.86,-31.102) -3.34,-30.581 ccw(c-3.86,-31.102) -3.86,-30.366 ; -3.86,-30.366 ccw(c-3.86,-29.63) -3.34,-30.15 cw(c-3.86,-29.63) -3.86,-30.366 ; -3.029,-3.65 cw(c-4.164,-3.65) -3.362,-4.452 ccw(c-4.164,-3.65) -3.029,-3.65 ; -3.029,-3.65 ccw(c-1.895,-3.65) -2.697,-4.452 cw(c-1.895,-3.65) -3.029,-3.65 ; -2.388,-30.366 cw(c-2.388,-29.63) -2.909,-30.15 ccw(c-2.388,-29.63) -2.388,-30.366 ; -2.388,-30.366 ccw(c-2.388,-31.102) -2.909,-30.581 cw(c-2.388,-31.102) -2.388,-30.366 ; -2.082,-30.366 cw(c-2.082,-31.102) -1.562,-30.581 ccw(c-2.082,-31.102) -2.082,-30.366 ; -2.082,-30.366 ccw(c-2.082,-29.63) -1.562,-30.15 cw(c-2.082,-29.63) -2.082,-30.366 ; -0.61,-30.366 cw(c-0.61,-29.63) -1.131,-30.15 ccw(c-0.61,-29.63) -0.61,-30.366 ; -0.61,-30.366 ccw(c-0.61,-31.102) -1.131,-30.581 cw(c-0.61,-31.102) -0.61,-30.366 ; 5.539,-6.477 cw(c5.539,-7.06) 5.951,-6.648 ccw(c5.539,-7.06) 5.539,-6.477 ; 5.539,-6.477 ccw(c5.539,-5.894) 5.951,-6.306 cw(c5.539,-5.894) 5.539,-6.477 ; 6.426,-4.447 cw(c5.844,-4.447) 6.256,-4.859 ccw(c5.844,-4.447) 6.426,-4.447 ; 6.426,-4.447 ccw(c7.009,-4.447) 6.597,-4.859 cw(c7.009,-4.447) 6.426,-4.447 ; 8.255,-7.999 cw(c8.838,-7.999) 8.426,-7.587 ccw(c8.838,-7.999) 8.255,-7.999 ; 8.255,-7.999 ccw(c7.672,-7.999) 8.084,-7.587 cw(c7.672,-7.999) 8.255,-7.999 ; U9.6@-15.788,-35.047 ccw(c-14.921,-34.266) -14.921,-35.433 cw(c-14.921,-34.266) U9.6@-15.788,-35.047 ; U9.6@-15.58,-34.86 ccw(c-14.293,-33.701) -14.293,-35.433 cw(c-14.293,-33.701) U9.6@-15.58,-34.86 ; U9.6@-15.456,-35.101 ccw(c-14.881,-34.974) -15.034,-35.542 cw(c-14.881,-34.974) U9.6@-15.456,-35.101 ; U9.6@-15.402,-35.792 cw(c-14.536,-36.658) -14.536,-35.433 ccw(c-14.536,-36.658) U9.6@-15.402,-35.792 ; C3.2@-15.265,-11.592 cw(c-15.265,-12.342) -14.736,-11.812 ccw(c-15.265,-12.342) C3.2@-15.265,-11.592 ; C2.2@-11.369,-4.521 cw(c-10.62,-4.521) -11.15,-3.991 ccw(c-10.62,-4.521) C2.2@-11.369,-4.521 ; Y1.4@-5.075,-7.537 cw(c-6.137,-8.599) -4.635,-8.599 ccw(c-6.137,-8.599) Y1.4@-5.075,-7.537 ; Y1.4@-4.878,-7.34 cw(c-5.463,-7.924) -4.635,-7.924 ccw(c-5.463,-7.924) Y1.4@-4.878,-7.34 ; C16.2@-4.703,-30.505 cw(c-4.367,-30.84) -4.367,-30.366 ccw(c-4.367,-30.84) C16.2@-4.703,-30.505 ; C16.2@-4.703,-30.207 ccw(c-4.32,-29.825) -4.32,-30.366 cw(c-4.32,-29.825) C16.2@-4.703,-30.207 ; -4.635,-8.079 cw(c-3.868,-8.079) -4.411,-7.537 ccw(c-3.868,-8.079) -4.635,-8.079 ; C10.1@-3.384,-2.976 cw(c-4.24,-3.832) -3.029,-3.832 ccw(c-4.24,-3.832) C10.1@-3.384,-2.976 ; C10.1@-3.187,-2.779 cw(c-3.566,-3.158) -3.029,-3.158 ccw(c-3.566,-3.158) C10.1@-3.187,-2.779 ; -0.252,-30.366 ccw(c-0.252,-29.825) 0.131,-30.207 cw(c-0.252,-29.825) -0.252,-30.366 ; -0.205,-30.366 cw(c-0.205,-30.84) 0.131,-30.505 ccw(c-0.205,-30.84) -0.205,-30.366
  Top Layer w0.305: R20.1@-16.18,-17.678 U7.1@-13.157,-17.678 ; v1(-10.16,-31.039) -10.16,-30.048 -9.771,-29.659 U10.2@-9.246,-29.659 ; -14.49,-17.678 cw(c-14.49,-18.046) -14.23,-17.786 ccw(c-14.49,-18.046) -14.49,-17.678 ; -14.49,-17.678 ccw(c-14.49,-17.31) -14.23,-17.571 cw(c-14.49,-17.31) -14.49,-17.678 ; -10.16,-30.487 cw(c-10.712,-30.487) -10.322,-30.877 ccw(c-10.712,-30.487) -10.16,-30.487 ; -10.16,-30.487 ccw(c-9.608,-30.487) -9.998,-30.877 cw(c-9.608,-30.487) -10.16,-30.487 ; R20.1@-16.065,-17.793 cw(c-15.789,-18.069) -15.789,-17.678 ccw(c-15.789,-18.069) R20.1@-16.065,-17.793 ; R20.1@-16.065,-17.513 ccw(c-15.667,-17.115) -15.667,-17.678 cw(c-15.667,-17.115) R20.1@-16.065,-17.513
  Top Layer w0.381: U7.6@-7.569,-20.218 -5.944,-20.218 -5.791,-20.066 v1@-4.826,-20.066 ; -5.322,-20.066 cw(c-5.322,-20.613) -4.935,-20.226 ccw(c-5.322,-20.613) -5.322,-20.066 ; -5.199,-20.066 ccw(c-5.199,-19.693) -4.935,-19.957 cw(c-5.199,-19.693) -5.199,-20.066
  Top Layer w0.457: U9.5@-13.157,-39.248 -12.137,-39.248 -11.227,-40.157 -10.389,-40.157
  Top Layer w0.508: C14.2@-16.256,-30.48 -16.256,-32.182 -15.977,-32.461 U9.6@-15.977,-34.976 U9.11@-15.977,-37.109 U9.10@-15.977,-38.785 U9.9@-15.977,-40.898 -15.527,-40.448 U9.8@-13.665,-40.448 ; U7.3@-13.157,-20.218 -10.998,-20.218 U7.0@-10.363,-19.583 -9.728,-20.218 U7.6@-7.569,-20.218 ; U7.3@-12.442,-20.218 cw(c-12.442,-22.412) U7.0@-10.891,-20.861 ; -11.887,-20.218 ccw(c-11.887,-18.81) U7.0@-10.891,-19.806 ; U7.0@-9.836,-20.861 cw(c-8.285,-22.412) U7.6@-8.285,-20.218 ; U7.0@-9.836,-19.806 ccw(c-8.84,-18.81) -8.84,-20.218 ; v1(23.749,-44.196) 24.562,-44.196 24.763,-44.397 U4.0@26.924,-44.397 ; v1(25.578,-36.347) 25.578,-34.62 25.77,-34.428 U3.10@25.77,-33.003 ; U3.10@25.705,-33.068 U3.10@25.77,-33.003 ; v1(25.933,-30.886) 25.959,-30.912 25.959,-31.616 25.835,-31.74 25.835,-32.938 U3.10@25.77,-33.003 ; U4.0@26.679,-44.642 ccw(c26.089,-45.233) 26.089,-44.397 ccw(c26.089,-43.562) U4.0@26.679,-44.153 ; v1(27.915,-30.886) 27.915,-31.699 27.97,-31.755 U3.12@27.97,-33.003 ; v1(27.915,-22.962) 27.915,-22.098 27.97,-22.043 U3.13@27.97,-20.803 27.97,-19.537 27.915,-19.482 v1(27.915,-18.669) ; -16.256,-31.943 cw(c-15.059,-31.943) -15.905,-31.097 ccw(c-15.059,-31.943) -16.256,-31.943 ; -16.256,-31.943 ccw(c-17.453,-31.943) -16.607,-31.097 cw(c-17.453,-31.943) -16.256,-31.943 ; -15.977,-39.613 cw(c-15.149,-39.613) -15.734,-39.028 ccw(c-15.149,-39.613) -15.977,-39.613 ; -15.977,-39.613 ccw(c-16.804,-39.613) -16.219,-39.028 cw(c-16.804,-39.613) -15.977,-39.613 ; U9.10@-15.977,-38.97 cw(c-17.663,-38.97) -16.471,-40.162 ccw(c-17.663,-38.97) U9.10@-15.977,-38.97 ; U9.10@-15.977,-38.97 ccw(c-14.29,-38.97) U9.9@-15.483,-40.162 ; U9.10@-15.977,-38.97 ccw(c-14.29,-38.97) U9.9@-15.483,-40.162 ; -15.977,-37.957 cw(c-16.804,-37.957) -16.219,-38.543 ccw(c-16.804,-37.957) -15.977,-37.957 ; -15.977,-37.957 ccw(c-15.149,-37.957) -15.734,-38.543 cw(c-15.149,-37.957) -15.977,-37.957 ; -15.977,-37.937 cw(c-15.149,-37.937) -15.734,-37.352 ccw(c-15.149,-37.937) -15.977,-37.937 ; -15.977,-37.937 ccw(c-16.804,-37.937) -16.219,-37.352 cw(c-16.804,-37.937) -15.977,-37.937 ; U9.11@-15.977,-36.903 cw(c-14.29,-36.903) -15.483,-35.711 ccw(c-14.29,-36.903) U9.11@-15.977,-36.903 ; U9.11@-15.977,-36.903 ccw(c-17.663,-36.903) -16.471,-35.711 cw(c-17.663,-36.903) U9.11@-15.977,-36.903 ; -15.977,-36.282 cw(c-16.804,-36.282) -16.219,-36.867 ccw(c-16.804,-36.282) -15.977,-36.282 ; -15.977,-36.282 ccw(c-15.149,-36.282) -15.734,-36.867 cw(c-15.149,-36.282) -15.977,-36.282 ; -15.977,-33.048 cw(c-17.663,-33.048) -16.471,-34.241 ccw(c-17.663,-33.048) -15.977,-33.048 ; -15.977,-33.048 ccw(c-14.29,-33.048) -15.483,-34.241 cw(c-14.29,-33.048) -15.977,-33.048 ; U9.9@-15.483,-40.162 ccw(c-14.794,-39.474) -14.794,-40.448 cw(c-14.794,-39.474) U9.9@-15.483,-40.162 ; U9.9@-15.166,-40.448 cw(c-15.166,-41.643) -14.32,-40.798 ccw(c-15.166,-41.643) U9.9@-15.166,-40.448 ; U9.9@-15.166,-40.448 ccw(c-15.166,-39.252) -14.32,-40.097 cw(c-15.166,-39.252) U9.9@-15.166,-40.448 ; U9.8@-14.582,-40.291 cw(c-14.873,-39.204) -15.554,-40.1 ccw(c-14.873,-39.204) U9.8@-14.582,-40.291 ; U9.8@-14.582,-40.291 ccw(c-14.283,-41.404) -15.338,-40.939 cw(c-14.283,-41.404) U9.8@-14.582,-40.291 ; U9.9@-15.842,-40.791 cw(c-15.013,-41.62) -15.013,-40.448 ccw(c-15.013,-41.62) U9.9@-15.842,-40.791 ; U9.9@-15.483,-41.15 cw(c-13.786,-42.846) -13.786,-40.448 ccw(c-13.786,-42.846) U9.9@-15.483,-41.15 ; U9.9@-15.065,-40.79 ccw(c-15.321,-39.837) -14.421,-40.243 cw(c-15.321,-39.837) U9.9@-15.065,-40.79 ; -15.002,-40.773 cw(c-14.734,-41.772) -14.218,-40.877 ccw(c-14.734,-41.772) -15.002,-40.773
  Top Layer w0.635: P3.2@5.001,3.556 5.385,3.94 C13.1@5.385,6.426 ; C13.1@5.01,5.944 cw(c3.622,5.142) 5.17,4.727 ; 5.184,4.709 ccw(c5.782,4.363) P3.2@5.302,3.867 ; 5.385,5.116 cw(c6.429,5.116) 5.691,5.854 ccw(c6.429,5.116) 5.385,5.116 ; 5.385,5.116 ccw(c4.341,5.116) 5.079,5.854 cw(c4.341,5.116) 5.385,5.116 ; P3.2@4.695,3.862 ccw(c3.03,5.527) 5.385,5.527 cw(c3.03,5.527) P3.2@4.695,3.862
  Bottom Layer w0.279: C8.2@5.131,-6.938 5.591,-6.477 ; C8.2@5.237,-6.656 ccw(c5.411,-6.357) 5.655,-6.602 ; C21.2@6.405,-3.894 6.426,-3.915 v1(6.426,-5.029) ; v1(8.255,-7.417) 8.255,-7.955 ; C20.2@8.885,-8.585 8.255,-7.955 ; 5.591,-6.477 cw(c5.591,-6.938) 5.939,-6.635 ccw(c5.591,-6.938) 5.591,-6.477 ; 5.591,-6.477 ccw(c5.591,-6.016) 5.939,-6.319 cw(c5.591,-6.016) 5.591,-6.477 ; 5.591,-6.477 cw(c5.217,-6.102) 5.155,-6.629 ccw(c5.217,-6.102) 5.591,-6.477 ; 5.591,-6.477 v1(6.121,-6.477) ; 5.654,-6.602 cw(c5.748,-6.954) v1@5.973,-6.667 ; 5.654,-6.602 ccw(c5.56,-6.25) v1@5.898,-6.387 ; 5.654,-6.602 cw(c5.748,-6.954) v1@5.973,-6.667 ; 5.654,-6.602 ccw(c5.56,-6.25) v1@5.898,-6.387 ; 5.654,-6.602 ccw(c5.56,-6.25) v1@5.898,-6.387 ; 5.654,-6.602 cw(c5.748,-6.954) v1@5.973,-6.667 ; v1(6.121,-6.477) ccw(c6.121,-7.412) 5.313,-6.943 cw(c6.121,-7.412) v1(6.121,-6.477) ; 6.426,-4.447 cw(c5.844,-4.447) 6.256,-4.859 ccw(c5.844,-4.447) 6.426,-4.447 ; 6.426,-4.447 ccw(c7.009,-4.447) 6.597,-4.859 cw(c7.009,-4.447) 6.426,-4.447 ; 8.255,-7.955 cw(c8.734,-7.955) 8.415,-7.597 ccw(c8.734,-7.955) 8.255,-7.955 ; 8.255,-7.955 ccw(c7.776,-7.955) 8.095,-7.597 cw(c7.776,-7.955) 8.255,-7.955 ; C8.2@5.071,-6.803 cw(c5.637,-7.131) 5.637,-6.477 ccw(c5.637,-7.131) C8.2@5.071,-6.803 ; C21.2@6.257,-4.043 cw(c5.847,-4.452) 6.426,-4.452 ccw(c5.847,-4.452) C21.2@6.257,-4.043 ; 6.426,-4.352 cw(c6.863,-4.352) 6.554,-4.043 ccw(c6.863,-4.352) 6.426,-4.352 ; 8.356,-8.055 cw(c7.826,-8.585) 8.575,-8.585 ccw(c7.826,-8.585) 8.356,-8.055
  other v1: -0.838,-44.196 1.143,-44.196 15.494,-44.196 17.475,-44.196 19.456,-44.196 21.438,-44.196 23.749,-42.215 23.749,-40.234 28.524,-39.599 22.352,-38.608 -6.274,-38.481 -3.607,-38.481 -0.864,-38.481 28.524,-37.617 -6.274,-36.5 28.524,-35.636 -6.274,-34.519 12.065,-32.868 -6.274,-32.537 -2.515,-32.36 -0.533,-32.36 1.448,-32.36 12.065,-30.886 14.046,-30.886 16.027,-30.886 18.009,-30.886 19.99,-30.886 21.971,-30.886 23.952,-30.886 12.065,-28.905 14.046,-28.905 18.009,-28.905 23.952,-28.905 27.915,-28.905 -16.027,-27.305 12.065,-26.924 14.046,-26.924 18.009,-26.924 23.952,-26.924 27.915,-26.924 -16.027,-25.324 -11.1,-25.324 -9.119,-25.324 12.065,-24.943 14.046,-24.943 18.009,-24.943 23.952,-24.943 27.915,-24.943 -16.027,-23.343 1.346,-23.114 12.065,-22.962 14.046,-22.962 16.027,-22.962 18.009,-22.962 19.99,-22.962 21.971,-22.962 23.952,-22.962 25.933,-22.962 -16.027,-21.361 12.065,-20.98 4.623,-19.279 19.99,-18.669 21.971,-18.669 23.952,-18.669 25.933,-18.669 -7.671,-14.453 -16.002,-14.427 1.626,-12.725 -7.671,-12.471 11.938,-10.744 26.518,-10.566 -7.671,-10.49 26.518,-8.585 -7.671,-8.509 26.518,-6.604 -7.671,-6.528 -16.002,-6.477 18.796,-4.771 26.518,-4.623 -7.671,-4.547 -16.002,-4.496 26.518,-2.642 -7.671,-2.565 -16.002,-2.515 1.6,-1.499 26.518,-0.66 -7.671,-0.584 -16.002,-0.533 9.474,0.152 11.989,0.152 26.518,1.321 -8.814,6.426 -6.833,6.426 -3.632,6.426 -1.651,6.426 0.33,6.426 16.408,6.426 18.39,6.426 20.371,6.426 22.352,6.426 -14.173,9.068 -14.173,11.049 -14.173,13.03 -14.173,15.011 -14.884,20.269 -12.903,20.269
KEY0: U6.29
KEY1: U6.33
KEY2: R14.2 S1.3 U6.17 | length 34.9
  Top Layer w0.279: U6.17@6.558,-10.866 6.558,-12.172 7.62,-13.233 v1(7.62,-29.565) ; S1.3@9.521,-34.159 9.521,-36.115 10.698,-37.292 R14.2@12.243,-37.292 ; 7.62,-28.983 cw(c7.037,-28.983) 7.449,-29.395 ccw(c7.037,-28.983) 7.62,-28.983 ; 7.62,-28.983 ccw(c8.203,-28.983) 7.791,-29.395 cw(c8.203,-28.983) 7.62,-28.983 ; 11.735,-37.292 cw(c11.735,-37.8) 12.094,-37.441 ccw(c11.735,-37.8) 11.735,-37.292 ; 11.735,-37.292 ccw(c11.735,-36.784) 12.094,-37.143 cw(c11.735,-36.784) 11.735,-37.292
  Bottom Layer w0.279: v1(7.62,-29.565) 7.62,-32.258 S1.3@9.521,-34.159 ; 7.62,-30.148 cw(c8.203,-30.148) 7.791,-29.736 ccw(c8.203,-30.148) 7.62,-30.148 ; 7.62,-30.148 ccw(c7.037,-30.148) 7.449,-29.736 cw(c7.037,-30.148) 7.62,-30.148
NetC2_1: C2.1 C17.1 S6.1 U1.1 U1.3 | length 43.5
  Top Layer w0.508: -13.227,-4.08 cw(c-13.702,-4.354) C2.1@-13.172,-4.496 ; U1.1@-10.897,-6.858 -10.897,-7.874 -11.328,-8.306 -12.344,-8.306 -12.797,-7.854 U1.3@-12.797,-6.858 -12.797,-4.704 C2.1@-12.979,-4.521 -13.31,-4.191 C17.1@-13.31,-1.245 -13.31,1.092 -11.506,2.896 -11.506,13.665 -9.119,16.053 -9.119,18.269 S6.1@-10.379,19.53 ; -13.31,-2.708 cw(c-12.112,-2.708) -12.959,-1.861 ccw(c-12.112,-2.708) -13.31,-2.708 ; -13.31,-2.708 ccw(c-14.507,-2.708) -13.66,-1.861 cw(c-14.507,-2.708) -13.31,-2.708 ; -13.31,0.219 cw(c-14.507,0.219) -13.66,-0.628 ccw(c-14.507,0.219) -13.31,0.219 ; -13.31,0.219 ccw(c-12.112,0.219) -12.959,-0.628 cw(c-12.112,0.219) -13.31,0.219 ; -13.31,-3.734 ccw(c-12.292,-3.734) -13.012,-4.453 cw(c-12.292,-3.734) -13.31,-3.734 ; C2.1@-12.947,-4.589 cw(c-13.311,-4.953) -12.797,-4.953 ccw(c-13.311,-4.953) C2.1@-12.947,-4.589
NetC3_1: C3.1 U1.4 | length 4.5
  Top Layer w0.279: C3.1@-15.265,-9.982 -14.841,-9.558 ; U1.4@-12.797,-9.558 -14.841,-9.558 ; -14.841,-9.558 cw(c-15.144,-9.255) -15.225,-9.676 ccw(c-15.144,-9.255) -14.841,-9.558 ; -13.123,-9.558 cw(c-13.123,-9.885) -12.892,-9.654 ccw(c-13.123,-9.885) -13.123,-9.558 ; -13.123,-9.558 ccw(c-13.123,-9.231) -12.892,-9.462 cw(c-13.123,-9.231) -13.123,-9.558
NetC11_1: C11.1 L1.1 U4.1 | length 5.2
  Top Layer w0.33: U4.1@26.873,-40.947 U4.1@26.924,-40.997
  Top Layer w0.711: U4.1@26.873,-40.947 C11.1@26.873,-37.067 ; 26.873,-40.185 ccw(c27.637,-40.185) 27.097,-40.725 cw(c27.637,-40.185) 26.873,-40.185
NetC15_2: C15.2 C16.1 U8.6 | length 13.8
  Top Layer w0.305: C16.1@-4.851,-28.956 -3.365,-28.956 C15.2@-3.124,-28.715 -3.124,-25.552 -2.144,-24.573 U8.6@-0.991,-24.573 ; -3.778,-28.83 cw(c-3.628,-29.09) C15.2@-3.373,-28.932 ; -4.374,-28.956 cw(c-4.374,-28.479) -4.712,-28.816 ccw(c-4.374,-28.479) -4.374,-28.956 ; -4.374,-28.956 ccw(c-4.374,-29.433) -4.712,-29.096 cw(c-4.374,-29.433) -4.374,-28.956 ; -3.124,-27.946 cw(c-3.829,-27.946) -3.331,-28.445 ccw(c-3.829,-27.946) -3.124,-27.946 ; -3.124,-27.946 ccw(c-2.419,-27.946) -2.918,-28.445 cw(c-2.419,-27.946) -3.124,-27.946 ; -4.259,-28.956 ccw(c-4.259,-27.644) -3.331,-28.572 cw(c-4.259,-27.644) -4.259,-28.956
NetD1_1: D1.1 R13.1 | length 3.7
  Top Layer w0.381: D1.1@23.139,-16.358 R13.1@25.603,-16.358 ; 25.118,-16.358 cw(c25.118,-16.743) 25.39,-16.47 ccw(c25.118,-16.743) 25.118,-16.358 ; 25.118,-16.358 ccw(c25.118,-15.973) 25.39,-16.245 cw(c25.118,-15.973) 25.118,-16.358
